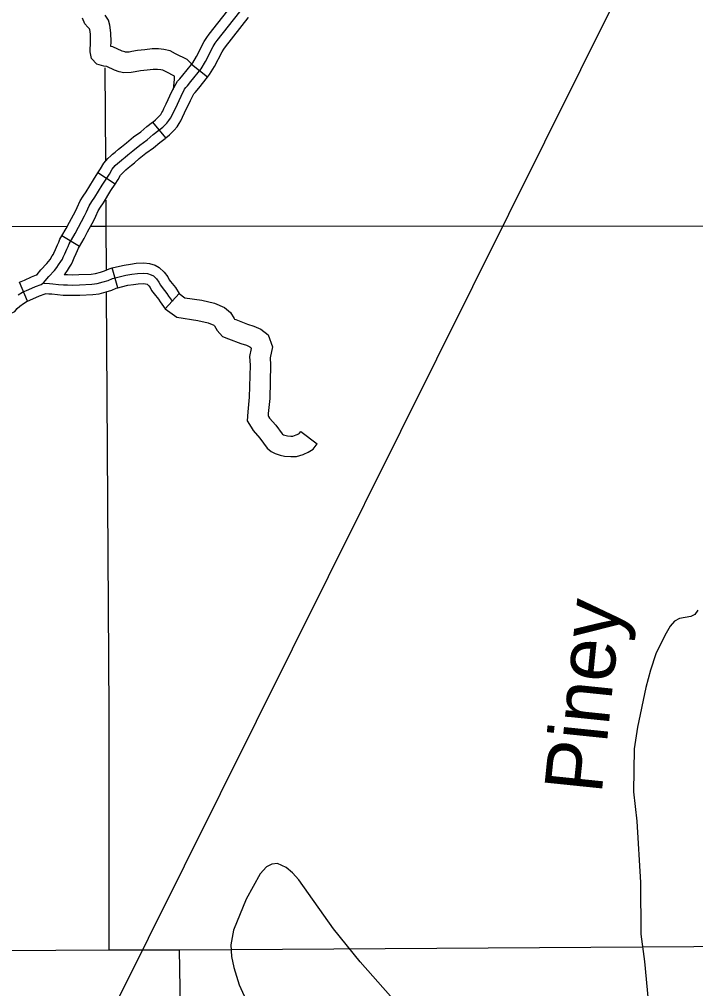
# Model space of a CAD drawing. Extents: x 1377389 to 1380723, y 1168351 to 1170484.
# Drawn here: x 1379187.9 to 1379286.7, y 1169316 to 1169457.7 of the extents above; entities that cross this region are included whole.
import ezdxf

# ---------------------------------------------------------------- set-up
doc = ezdxf.new("R2010")
doc.units = 0
doc.layers.add('B_Contour_Elevations', color=7, linetype='Continuous')
doc.layers.add('B_Fill', color=7, linetype='Continuous')

msp = doc.modelspace()

# ---------------------------------------------------------------- linework, layer by layer
at = {"layer": 'B_Contour_Elevations'}
msp.add_line((1379393.4, 1169698.55), (1379117.79, 1169144.53), dxfattribs=at)
at = {"layer": 'B_Fill'}
for p, q in [((1379215.41, 1169449.2), (1379213.07, 1169451.08)), ((1379209.32, 1169440.33), (1379207.42, 1169442.65)), ((1379201.92, 1169433.59), (1379199.4, 1169435.22)), ((1379196.72, 1169424.49), (1379194.13, 1169426.01)), ((1379202.29, 1169418.44), (1379201.47, 1169421.33)), ((1379189.11, 1169416.48), (1379187.92, 1169419.24))]:
    msp.add_line(p, q, dxfattribs=at)
for points in [[(1379213.07, 1169451.08), (1379213.25, 1169451.31), (1379213.82, 1169452.25), (1379214.93, 1169454.41), (1379215.29, 1169455.01), (1379215.65, 1169455.48), (1379218.93, 1169459.66), (1379218.95, 1169459.69)], [(1379187.72, 1169417.41), (1379188.38, 1169417.8), (1379189.3, 1169418.2), (1379190.27, 1169418.65), (1379191.09, 1169418.94), (1379191.51, 1169419.19), (1379191.71, 1169419.44), (1379192.2, 1169420.09), (1379193.07, 1169420.98), (1379193.39, 1169421.38), (1379193.66, 1169421.77), (1379193.96, 1169422.27), (1379194.21, 1169422.62), (1379194.33, 1169422.91), (1379194.56, 1169423.41), (1379194.85, 1169424.08), (1379195.05, 1169424.48), (1379195.2, 1169424.87), (1379196.09, 1169426.39), (1379196.56, 1169427.3), (1379197.46, 1169428.94), (1379197.73, 1169429.54), (1379198.13, 1169430.41), (1379198.52, 1169431.03), (1379198.94, 1169431.67), (1379200.03, 1169433.43), (1379201.08, 1169435.04), (1379201.47, 1169435.76), (1379201.94, 1169436.29), (1379202.29, 1169436.63), (1379202.49, 1169436.81), (1379202.88, 1169437.13), (1379203.36, 1169437.53), (1379203.78, 1169437.87), (1379204.5, 1169438.47), (1379205.51, 1169439.29), (1379206.6, 1169440.06), (1379207.49, 1169440.82), (1379208.31, 1169441.45), (1379208.86, 1169441.89), (1379209.25, 1169442.31), (1379209.45, 1169442.51), (1379209.77, 1169442.88), (1379210, 1169443.23), (1379210.2, 1169443.55), (1379210.39, 1169444), (1379210.72, 1169444.65), (1379211.56, 1169446.46), (1379212.07, 1169447.45), (1379212.24, 1169447.71), (1379212.48, 1169447.97), (1379212.97, 1169448.56), (1379214.48, 1169450.45), (1379215.13, 1169451.52), (1379216.24, 1169453.68), (1379216.54, 1169454.17), (1379216.84, 1169454.57), (1379220.14, 1169458.76)], [(1379210.43, 1169447.41), (1379210.57, 1169448.94), (1379210.58, 1169449.35), (1379209.35, 1169449.98), (1379208.88, 1169450.22), (1379208.57, 1169450.3), (1379208.1, 1169450.34), (1379207.48, 1169450.34), (1379206.59, 1169450.24), (1379205.6, 1169450.13), (1379204.86, 1169449.99), (1379204.24, 1169449.9), (1379203.18, 1169449.85), (1379202.51, 1169450.01), (1379201.8, 1169450.24), (1379200.7, 1169450.76), (1379200.28, 1169450.83), (1379199.26, 1169451.11), (1379198.48, 1169451.95), (1379198.25, 1169452.92), (1379198.31, 1169454.43), (1379198.3, 1169455.48), (1379198.21, 1169456.18), (1379198.19, 1169456.25), (1379198.18, 1169456.26), (1379197.91, 1169456.5), (1379197.47, 1169457.01), (1379197.13, 1169457.84)], [(1379213.06, 1169451.16), (1379213.02, 1169451.22), (1379212.43, 1169451.78), (1379210.73, 1169452.64), (1379209.95, 1169453.05), (1379209.05, 1169453.27), (1379208.23, 1169453.34), (1379207.31, 1169453.34), (1379206.27, 1169453.22), (1379205.16, 1169453.1), (1379204.37, 1169452.95), (1379203.96, 1169452.89), (1379203.45, 1169452.87), (1379203.32, 1169452.9), (1379202.92, 1169453.03), (1379201.6, 1169453.65), (1379201.29, 1169453.7), (1379201.31, 1169454.39), (1379201.29, 1169455.68), (1379201.16, 1169456.82), (1379200.93, 1169457.55), (1379200.46, 1169458.27)], [(1379215.41, 1169449.2), (1379215.72, 1169449.59), (1379216.44, 1169450.78), (1379217.55, 1169452.94), (1379217.79, 1169453.33), (1379218.03, 1169453.66), (1379221.34, 1169457.87), (1379221.41, 1169457.97)], [(1379200.4, 1169450.6), (1379200.49, 1169437.11)], [(1379207.42, 1169442.65), (1379207.83, 1169442.99), (1379208.18, 1169443.36), (1379208.35, 1169443.53), (1379208.57, 1169443.78), (1379208.73, 1169444.03), (1379208.87, 1169444.25), (1379209.04, 1169444.64), (1379209.37, 1169445.3), (1379210.21, 1169447.12), (1379210.77, 1169448.2), (1379211.05, 1169448.63), (1379211.35, 1169448.96), (1379211.81, 1169449.51), (1379213.07, 1169451.08)], [(1379209.32, 1169440.33), (1379209.88, 1169440.79), (1379210.33, 1169441.27), (1379210.55, 1169441.49), (1379210.98, 1169441.98), (1379211.27, 1169442.43), (1379211.53, 1169442.85), (1379211.75, 1169443.36), (1379212.07, 1169443.99), (1379212.91, 1169445.8), (1379213.37, 1169446.7), (1379213.43, 1169446.79), (1379213.61, 1169446.98), (1379214.13, 1169447.62), (1379215.41, 1169449.2)], [(1379199.4, 1169435.22), (1379199.79, 1169435.81), (1379200.24, 1169436.64), (1379200.85, 1169437.32), (1379201.26, 1169437.73), (1379201.52, 1169437.95), (1379201.93, 1169438.28), (1379202.39, 1169438.68), (1379202.82, 1169439.03), (1379203.55, 1169439.63), (1379204.61, 1169440.49), (1379205.68, 1169441.24), (1379206.55, 1169441.99), (1379207.38, 1169442.62), (1379207.42, 1169442.65)], [(1379201.92, 1169433.59), (1379202.36, 1169434.27), (1379202.7, 1169434.89), (1379203.03, 1169435.25), (1379203.32, 1169435.54), (1379203.46, 1169435.66), (1379203.84, 1169435.97), (1379204.32, 1169436.37), (1379204.73, 1169436.72), (1379205.44, 1169437.31), (1379206.42, 1169438.09), (1379207.53, 1169438.87), (1379208.44, 1169439.66), (1379209.24, 1169440.27), (1379209.32, 1169440.33)], [(1379194.13, 1169426.01), (1379194.78, 1169427.11), (1379195.24, 1169428.01), (1379196.11, 1169429.61), (1379196.36, 1169430.16), (1379196.8, 1169431.12), (1379197.26, 1169431.84), (1379197.68, 1169432.48), (1379198.77, 1169434.23), (1379199.4, 1169435.22)], [(1379196.72, 1169424.49), (1379197.41, 1169425.66), (1379197.89, 1169426.6), (1379198.8, 1169428.27), (1379199.09, 1169428.91), (1379199.45, 1169429.69), (1379199.78, 1169430.21), (1379200.21, 1169430.87), (1379201.3, 1169432.63), (1379201.92, 1169433.59)], [(1379200.53, 1169431.25), (1379200.56, 1169427.46)], [(1379153.7, 1169427.26), (1379194.94, 1169427.44)], [(1379198.31, 1169427.45), (1379200.56, 1169427.46)], [(1379200.56, 1169427.46), (1379306.65, 1169427.49)], [(1379200.56, 1169427.46), (1379200.6, 1169421.05)], [(1379187.92, 1169419.24), (1379188.69, 1169419.57), (1379189.7, 1169420.03), (1379190.44, 1169420.31), (1379190.51, 1169420.34), (1379190.53, 1169420.37), (1379191.07, 1169421.07), (1379191.95, 1169421.98), (1379192.19, 1169422.27), (1379192.4, 1169422.58), (1379192.71, 1169423.09), (1379192.89, 1169423.35), (1379192.96, 1169423.51), (1379193.19, 1169424.02), (1379193.5, 1169424.72), (1379193.68, 1169425.08), (1379193.84, 1169425.52), (1379194.13, 1169426.01)], [(1379194.48, 1169420.34), (1379194.59, 1169420.48), (1379194.93, 1169420.96), (1379195.22, 1169421.45), (1379195.53, 1169421.88), (1379195.71, 1169422.32), (1379195.93, 1169422.8), (1379196.21, 1169423.44), (1379196.43, 1169423.88), (1379196.56, 1169424.22), (1379196.72, 1169424.49)], [(1379194.45, 1169420.36), (1379194.96, 1169420.36), (1379195.69, 1169420.34), (1379196.63, 1169420.38), (1379198.41, 1169420.45), (1379199.02, 1169420.52), (1379199.76, 1169420.73), (1379200.38, 1169420.92), (1379201.03, 1169421.2), (1379201.47, 1169421.33)], [(1379201.47, 1169421.33), (1379202.11, 1169421.51), (1379203.21, 1169421.76), (1379204.15, 1169421.9), (1379205.01, 1169422.02), (1379206.11, 1169422.08), (1379206.95, 1169421.98), (1379207.74, 1169421.74), (1379208.37, 1169421.4), (1379209.1, 1169420.74), (1379209.59, 1169420.05), (1379209.81, 1169419.62), (1379210, 1169419.36), (1379210.71, 1169418.49), (1379211.25, 1169417.6), (1379209.21, 1169415.37)], [(1379191.47, 1169419.09), (1379192.33, 1169419.06), (1379192.82, 1169419.02), (1379193.66, 1169418.93), (1379194.38, 1169418.86), (1379194.94, 1169418.86), (1379195.71, 1169418.84), (1379196.7, 1169418.88), (1379198.52, 1169418.95), (1379199.31, 1169419.04), (1379200.18, 1169419.29), (1379200.9, 1169419.51), (1379201.53, 1169419.78), (1379202.48, 1169420.05), (1379203.49, 1169420.28), (1379204.37, 1169420.42), (1379205.16, 1169420.53), (1379206.06, 1169420.57), (1379206.64, 1169420.51), (1379207.16, 1169420.35), (1379207.5, 1169420.17), (1379207.97, 1169419.74), (1379208.31, 1169419.27), (1379208.53, 1169418.84), (1379208.8, 1169418.46), (1379209.48, 1169417.62), (1379209.73, 1169417.22), (1379210.28, 1169416.44)], [(1379191.69, 1169417.58), (1379192.24, 1169417.57), (1379192.68, 1169417.53), (1379193.51, 1169417.44), (1379194.31, 1169417.36), (1379194.92, 1169417.36), (1379195.72, 1169417.34), (1379196.76, 1169417.38), (1379198.63, 1169417.45), (1379199.6, 1169417.56), (1379200.61, 1169417.85), (1379201.42, 1169418.11), (1379202.04, 1169418.37), (1379202.29, 1169418.44)], [(1379202.29, 1169418.44), (1379202.85, 1169418.6), (1379203.77, 1169418.81), (1379204.59, 1169418.93), (1379205.3, 1169419.03), (1379206.01, 1169419.07), (1379206.34, 1169419.03), (1379206.58, 1169418.96), (1379206.63, 1169418.93), (1379206.84, 1169418.74), (1379207.03, 1169418.48), (1379207.25, 1169418.05), (1379207.61, 1169417.55), (1379208.25, 1169416.76), (1379208.48, 1169416.39), (1379209.21, 1169415.37)], [(1379179.85, 1169411.96), (1379180.57, 1169412.34), (1379181.64, 1169412.83), (1379182.25, 1169413.13), (1379182.89, 1169413.37), (1379183.21, 1169413.43), (1379183.99, 1169413.61), (1379184.66, 1169413.86), (1379185.23, 1169414.06), (1379185.93, 1169414.33), (1379186.33, 1169414.6), (1379186.51, 1169414.63), (1379187.24, 1169414.99), (1379187.58, 1169415.42), (1379187.99, 1169415.77), (1379188.53, 1169416.14), (1379189.07, 1169416.46), (1379189.11, 1169416.48)], [(1379189.11, 1169416.48), (1379189.91, 1169416.83), (1379190.84, 1169417.26), (1379191.69, 1169417.57)], [(1379200.62, 1169417.81), (1379200.97, 1169356.49), (1379200.98, 1169321.71)], [(1379211.25, 1169417.6), (1379212.08, 1169416.99), (1379214.56, 1169416.63), (1379216.43, 1169416.18), (1379217.91, 1169415.57), (1379218.76, 1169414.84), (1379219.29, 1169413.93), (1379219.36, 1169413.85), (1379219.55, 1169413.78), (1379221.26, 1169413.12), (1379222.18, 1169412.84), (1379223.18, 1169412.39), (1379224.27, 1169411.54), (1379224.89, 1169409.79), (1379224.58, 1169408.21), (1379224.64, 1169407.19), (1379224.5, 1169402.27), (1379224.3, 1169400.06), (1379224.27, 1169399.74), (1379224.33, 1169399.64), (1379224.49, 1169399.39), (1379225.39, 1169398.35), (1379226.31, 1169397.1), (1379226.36, 1169397.07), (1379226.53, 1169396.97), (1379226.89, 1169396.84), (1379227.08, 1169396.8), (1379227.61, 1169396.76), (1379227.89, 1169396.77), (1379228.38, 1169396.93), (1379228.76, 1169397.1), (1379228.81, 1169397.13), (1379229.04, 1169397.43), (1379231.44, 1169395.64)], [(1379209.21, 1169415.37), (1379210.92, 1169414.13), (1379213.99, 1169413.68), (1379215.5, 1169413.32), (1379216.32, 1169412.98), (1379216.42, 1169412.9), (1379216.84, 1169412.19), (1379217.58, 1169411.32), (1379218.48, 1169410.98), (1379220.28, 1169410.29), (1379221.12, 1169410.03), (1379221.61, 1169409.8), (1379221.74, 1169409.7), (1379221.79, 1169409.56), (1379221.56, 1169408.42), (1379221.64, 1169407.14), (1379221.51, 1169402.45), (1379221.31, 1169400.32), (1379221.2, 1169399.01), (1379221.78, 1169398.07), (1379222.06, 1169397.6), (1379223.05, 1169396.48), (1379224.13, 1169395), (1379224.72, 1169394.53), (1379225.31, 1169394.23), (1379226.04, 1169393.96), (1379226.66, 1169393.82), (1379227.58, 1169393.76), (1379228.42, 1169393.79), (1379229.38, 1169394.1), (1379229.49, 1169394.14), (1379230.13, 1169394.42), (1379230.86, 1169394.86), (1379231.44, 1169395.64)], [(1379287.06, 1169371.31), (1379286.62, 1169370.72), (1379286.05, 1169370.4), (1379284.4, 1169370.11), (1379283.67, 1169369.73), (1379283.02, 1169368.97), (1379282.24, 1169367.62), (1379280.95, 1169364.94), (1379280.13, 1169362.55), (1379279.47, 1169360.01), (1379278.26, 1169354.23)], [(1379278.26, 1169354.23), (1379277.74, 1169351.07), (1379277.67, 1169344.77), (1379278.17, 1169340.48), (1379278.69, 1169331.53), (1379278.74, 1169323.96), (1379279.27, 1169319.98), (1379280.23, 1169309.6)], [(1379254.74, 1169300.71), (1379237.7, 1169319.92), (1379233.8, 1169324.78), (1379228.75, 1169331.91), (1379227.82, 1169332.96), (1379226.93, 1169333.74), (1379225.62, 1169334.3), (1379224.82, 1169334.23), (1379224.04, 1169333.83), (1379223.09, 1169332.82), (1379221.06, 1169329.11), (1379219.2, 1169324.59), (1379218.83, 1169322.44), (1379218.94, 1169320.74), (1379219.27, 1169319.11), (1379220.03, 1169316.59), (1379221.55, 1169313.26)], [(1378969.38, 1169321.13), (1378989.27, 1169321.09), (1379001.13, 1169321.14), (1379096.54, 1169321.07), (1379107.79, 1169321.09), (1379200.98, 1169321.71), (1379211.33, 1169321.71), (1379309.03, 1169322.34), (1379318.77, 1169322.31), (1379331.4, 1169322.31)], [(1379213.25, 1169209.82), (1379211.33, 1169321.71)]]:
    msp.add_lwpolyline(points, dxfattribs=at)

# ---------------------------------------------------------------- texts
msp.add_text('Piney', height=8.448, rotation=84.0989, dxfattribs=at).set_placement((1379273, 1169344.35))

doc.saveas('drawing.dxf')
